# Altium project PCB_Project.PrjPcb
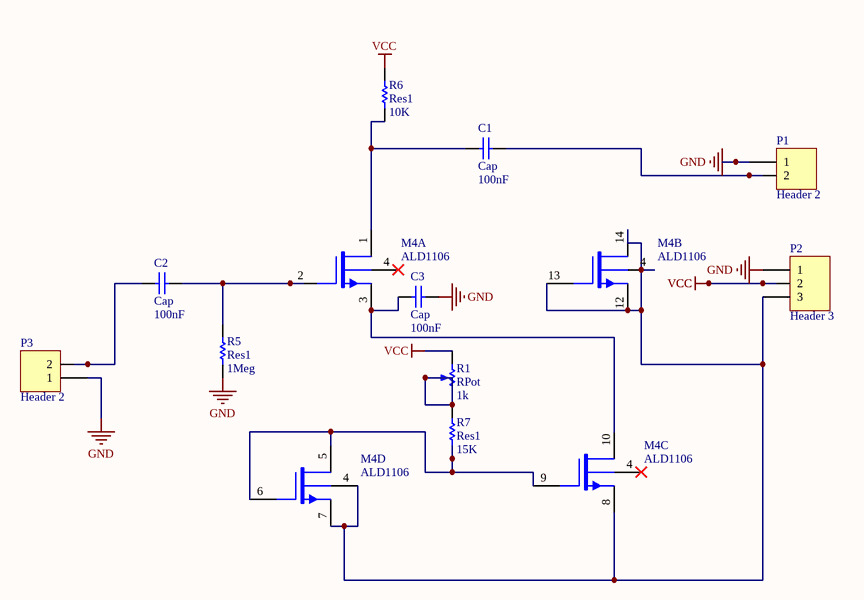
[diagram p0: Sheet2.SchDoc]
1 sheet, 11 parts. Net scope: global (net labels, ports and power ports of the same name join across sheets).
Board file: PCB2.PcbDoc

## Sheet Sheet2.SchDoc
size A4

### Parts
C1  Cap  value 100nF  [RAD-0.3]
C2  Cap  value 100nF  [RAD-0.3]
C3  Cap  value 100nF  [RAD-0.3]
M4  ALD1106  [DIP-14]  (parts A,B,C,D of 4)
P1  Header 2  [HDR1X2]
P2  Header 3  [HDR1X3]
P3  Header 2  [HDR1X2]
R1  RPot  value 1k  [VR5]
R5  Res1  value 1Meg  [AXIAL-0.3]
R6  Res1  value 10K  [AXIAL-0.3]
R7  Res1  value 15K  [AXIAL-0.3]

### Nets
GND: C3.2 P1.1 P2.1 P3.1 R5.1
VCC: P2.2 R1.1(TOP) R6.2
NetC1_1: C1.1 M4.1(DN1) R6.1
NetC1_2: C1.2 P1.2
NetC2_1: C2.1 P3.2
NetC2_2: C2.2 M4.2(GN1) R5.2
NetC3_1: C3.1 M4.3(SN1) M4.10(DN3)
NetM4_4: M4.4(V-) M4.7(SN4) M4.8(SN3) M4.12(SN2) M4.13(GN2) M4.14(DN2) P2.3
NetM4_5: M4.5(DN4) M4.6(GN4) M4.9(GN3) R7.1
NetR1_2: R1.2(TAP) R1.3(BOT) R7.2

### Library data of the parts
C1-C3 = Cap: Capacitor
M4 = ALD1106: Quad N-channel matched MOSFET array
P1 P3 = Header 2: Header, 2-Pin
P2 = Header 3: Header, 3-Pin
R1 = RPot: Potentiometer; Sim Note: Enter the Resistance value and the set point into parameter fields.; Set Position: 0.5
R5-R7 = Res1: Resistor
